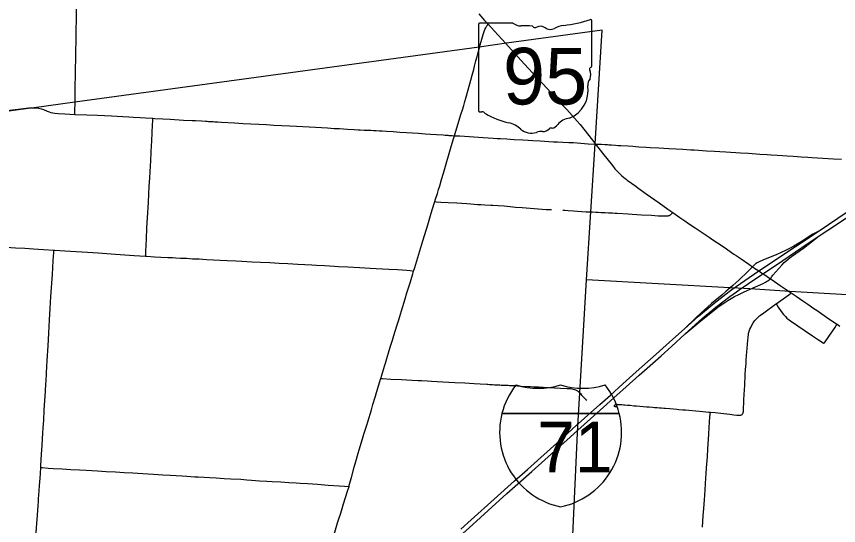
# Model space of a CAD drawing. Extents: x 9078 to 9739, y 4248 to 4966.
# Drawn here: x 9448.2 to 9549.3, y 4516.4 to 4579 of the extents above; entities that cross this region are included whole.
import ezdxf

# ---------------------------------------------------------------- set-up
doc = ezdxf.new("R2010")
doc.units = 0
for name, color, linetype in [('GM_X_County_Road', 7, 'Continuous'), ('GM_X_Interchange_Ramps', 7, 'Continuous'), ('GM_X_Interstate_Route', 7, 'Continuous'), ('GM_X_Interstate_Shield', 7, 'Continuous'), ('GM_X_State_Route', 7, 'Continuous'), ('GM_X_State_Shield', 7, 'Continuous'), ('GM_X_Township', 7, 'Continuous'), ('GM_X_Township_Road', 7, 'Continuous')]:
    doc.layers.add(name, color=color, linetype=linetype)

msp = doc.modelspace()

# ---------------------------------------------------------------- linework, layer by layer
at = {"layer": 'GM_X_County_Road'}
for points in [[(9505.17, 4575.29), (9505.23, 4575.54), (9505.43, 4576.26), (9505.6, 4576.81), (9505.73, 4577.2), (9505.82, 4577.42), (9505.92, 4577.65), (9506, 4577.79), (9506.07, 4577.9), (9506.12, 4577.97), (9506.2, 4578.08)], [(9502.08, 4564.37), (9502.16, 4564.65), (9502.49, 4565.75), (9502.9, 4567.08), (9503.04, 4567.56), (9503.21, 4568.1), (9503.35, 4568.58), (9503.46, 4568.97), (9503.76, 4570), (9504.09, 4571.18), (9504.26, 4571.81), (9504.45, 4572.53), (9504.55, 4572.93), (9504.71, 4573.56), (9504.86, 4574.12), (9505.07, 4574.91), (9505.17, 4575.29)], [(9499.66, 4556.26), (9499.75, 4556.55), (9499.97, 4557.26), (9500.11, 4557.73), (9500.25, 4558.2), (9500.49, 4558.99), (9500.72, 4559.77), (9500.88, 4560.32), (9501.14, 4561.19), (9501.35, 4561.9), (9501.6, 4562.76), (9501.93, 4563.86), (9502.08, 4564.37)], [(9519.43, 4563.34), (9520.16, 4563.31), (9520.57, 4563.29), (9520.9, 4563.27), (9521.06, 4563.25), (9521.4, 4563.23), (9521.86, 4563.2), (9522.2, 4563.18), (9522.23, 4563.18)], [(9522.23, 4563.18), (9522.53, 4563.16), (9523.43, 4563.1), (9524, 4563.06), (9524.74, 4563.01), (9525.64, 4562.96), (9526.13, 4562.93), (9527.19, 4562.87), (9528.42, 4562.8), (9529.32, 4562.74), (9530.14, 4562.7), (9531.12, 4562.64), (9531.53, 4562.62), (9532.1, 4562.58), (9533.08, 4562.52), (9534.06, 4562.46), (9534.71, 4562.43), (9535.45, 4562.37), (9536.02, 4562.34), (9536.67, 4562.3), (9537.25, 4562.27), (9538.23, 4562.2), (9539.62, 4562.1), (9540.52, 4562.04), (9541.01, 4562.02), (9541.74, 4561.97), (9542.4, 4561.92), (9542.97, 4561.88), (9543.71, 4561.84), (9544.69, 4561.77), (9545.51, 4561.72), (9546, 4561.69), (9546.73, 4561.65), (9548.7, 4561.52), (9549.68, 4561.46)], [(9497.05, 4547.7), (9497.18, 4548.16), (9498.19, 4551.45), (9498.62, 4552.87), (9498.78, 4553.42), (9499.04, 4554.28), (9499.21, 4554.83), (9499.57, 4556.01), (9499.66, 4556.26)], [(9437.86, 4551.19), (9438.03, 4551.18), (9438.28, 4551.17), (9438.93, 4551.13), (9439.91, 4551.07), (9440.89, 4551.02), (9441.96, 4550.95), (9444.25, 4550.82), (9445.64, 4550.73), (9446.95, 4550.65), (9448.1, 4550.59), (9449.24, 4550.53), (9450.31, 4550.46), (9451.53, 4550.38), (9452.8, 4550.3)], [(9451.19, 4523.54), (9451.21, 4523.8), (9451.3, 4525.19), (9451.36, 4526.25), (9451.45, 4527.81), (9451.49, 4528.38), (9451.55, 4529.36), (9451.61, 4530.59), (9451.66, 4531.24), (9451.73, 4532.31), (9451.77, 4532.96), (9451.82, 4533.86), (9451.84, 4534.19), (9451.9, 4535.17), (9451.95, 4535.99), (9451.99, 4536.72), (9452.09, 4538.53), (9452.17, 4540.08), (9452.27, 4541.72), (9452.35, 4543.11), (9452.44, 4544.58), (9452.62, 4547.28), (9452.67, 4548.1), (9452.72, 4549), (9452.78, 4549.98), (9452.8, 4550.3)], [(9452.8, 4550.3), (9452.93, 4550.3), (9454.15, 4550.21), (9456.93, 4550.03), (9458.24, 4549.94), (9460.37, 4549.79), (9462.66, 4549.64), (9464.09, 4549.54)], [(9464.09, 4549.54), (9464.22, 4549.54), (9465.2, 4549.48), (9465.94, 4549.44), (9466.83, 4549.39), (9467.41, 4549.37), (9467.82, 4549.35), (9468.39, 4549.32), (9469.13, 4549.29), (9469.86, 4549.24), (9470.68, 4549.2), (9471.58, 4549.15), (9474.12, 4549.02), (9475.19, 4548.97), (9475.92, 4548.94), (9477.15, 4548.87), (9478.21, 4548.82), (9479.36, 4548.75), (9480.51, 4548.69), (9481.57, 4548.63), (9482.8, 4548.56), (9484.52, 4548.47), (9485.09, 4548.43), (9486.07, 4548.38), (9487.3, 4548.32), (9487.79, 4548.29), (9488.94, 4548.22), (9490.41, 4548.14), (9491.72, 4548.07), (9492.46, 4548.03), (9494.01, 4547.94), (9495.08, 4547.89), (9496.22, 4547.83), (9496.63, 4547.79), (9496.88, 4547.76), (9497.05, 4547.7)], [(9493.01, 4534.51), (9493.12, 4534.9), (9493.46, 4536), (9493.58, 4536.39), (9493.84, 4537.25), (9493.96, 4537.65), (9494.18, 4538.35), (9494.44, 4539.22), (9494.6, 4539.77), (9494.77, 4540.32), (9495.01, 4541.1), (9495.21, 4541.73), (9495.42, 4542.43), (9495.55, 4542.82), (9496, 4544.31), (9496.22, 4545.02), (9496.61, 4546.27), (9496.95, 4547.37), (9497.05, 4547.7)], [(9541.62, 4543.67), (9542.5, 4544.3), (9543.17, 4544.78), (9543.36, 4544.93), (9543.48, 4545.02)], [(9538.3, 4540.28), (9538.32, 4540.33), (9538.4, 4540.56), (9538.5, 4540.78), (9538.65, 4541.07), (9538.81, 4541.35), (9538.9, 4541.49), (9539, 4541.62), (9539.16, 4541.8), (9539.34, 4541.97), (9539.58, 4542.19), (9539.71, 4542.29), (9540.11, 4542.58), (9541.57, 4543.63), (9541.62, 4543.67)], [(9541.62, 4543.67), (9541.7, 4543.56), (9541.87, 4543.29), (9542.25, 4542.75), (9542.54, 4542.36), (9542.65, 4542.23), (9542.76, 4542.11), (9542.93, 4541.94), (9543.12, 4541.79), (9543.39, 4541.6), (9546.1, 4539.76), (9546.84, 4539.25), (9547.41, 4538.87), (9547.46, 4538.86), (9547.5, 4538.85)], [(9547.5, 4538.85), (9547.55, 4538.87), (9547.59, 4538.9), (9548.11, 4539.65), (9548.48, 4540.19), (9548.85, 4540.74), (9549.03, 4541.02), (9549.13, 4541.18)], [(9537.64, 4531.51), (9537.66, 4531.85), (9537.71, 4532.59), (9537.73, 4533.08), (9537.77, 4533.73), (9537.79, 4534.14), (9537.81, 4534.47), (9537.84, 4535.04), (9537.88, 4535.61), (9537.93, 4536.35), (9537.96, 4536.84), (9537.99, 4537.25), (9538.03, 4537.82), (9538.06, 4538.14), (9538.1, 4538.8), (9538.13, 4539.12), (9538.17, 4539.61), (9538.21, 4539.85), (9538.25, 4540.09), (9538.3, 4540.28)], [(9489.1, 4521.23), (9489.14, 4521.37), (9489.4, 4522.32), (9489.75, 4523.58), (9489.94, 4524.3), (9490.23, 4525.32), (9490.34, 4525.72), (9490.63, 4526.66), (9490.85, 4527.36), (9490.94, 4527.65), (9491.1, 4528.14), (9491.29, 4528.77), (9491.41, 4529.16), (9491.85, 4530.66), (9492.04, 4531.29), (9492.35, 4532.31), (9492.49, 4532.78), (9492.78, 4533.72), (9492.99, 4534.43), (9493.01, 4534.51)], [(9493.01, 4534.51), (9493.2, 4534.5), (9494.26, 4534.43), (9495.57, 4534.36), (9496.88, 4534.3), (9497.62, 4534.26), (9498.03, 4534.24), (9498.76, 4534.2), (9499.25, 4534.17), (9500.64, 4534.09), (9502.12, 4534.01), (9503.34, 4533.95), (9504.49, 4533.89), (9505.23, 4533.84), (9506.04, 4533.79), (9506.19, 4533.79), (9506.36, 4533.78), (9506.53, 4533.77), (9506.76, 4533.76), (9506.98, 4533.74), (9507.22, 4533.73), (9507.43, 4533.72), (9507.63, 4533.71), (9507.81, 4533.7), (9508.01, 4533.69), (9508.16, 4533.68), (9508.35, 4533.67), (9508.49, 4533.67), (9508.68, 4533.66), (9508.82, 4533.65), (9509, 4533.64), (9509.55, 4533.62), (9509.8, 4533.6), (9510.05, 4533.58), (9510.29, 4533.57), (9511.19, 4533.52), (9511.43, 4533.51), (9511.84, 4533.49), (9512.41, 4533.46), (9512.99, 4533.44), (9513.64, 4533.4), (9515.11, 4533.33), (9515.93, 4533.29), (9516.34, 4533.26), (9516.5, 4533.24), (9516.66, 4533.2), (9516.82, 4533.15), (9516.97, 4533.09), (9517.12, 4533.01), (9517.19, 4532.97), (9517.26, 4532.93), (9517.32, 4532.89), (9517.38, 4532.83), (9517.44, 4532.78), (9517.51, 4532.7)], [(9517.51, 4532.7), (9517.55, 4532.66), (9517.71, 4532.47), (9517.92, 4532.22), (9518.09, 4532.05), (9518.22, 4531.92), (9518.33, 4531.82)], [(9535.2, 4530.2), (9535.56, 4530.16), (9535.94, 4530.11), (9536.41, 4530.05), (9536.81, 4530), (9536.88, 4530), (9537.12, 4529.97), (9537.21, 4529.98), (9537.29, 4530), (9537.37, 4530.03), (9537.44, 4530.08), (9537.5, 4530.14), (9537.54, 4530.21), (9537.57, 4530.3), (9537.6, 4530.46), (9537.61, 4530.62), (9537.62, 4530.97), (9537.64, 4531.39), (9537.64, 4531.51)], [(9532.58, 4516.22), (9532.67, 4517.61), (9532.74, 4518.51), (9532.81, 4519.58), (9532.84, 4520.15), (9532.89, 4520.8), (9532.95, 4521.54), (9532.99, 4522.27), (9533.03, 4522.76), (9533.08, 4523.5), (9533.14, 4524.4), (9533.17, 4524.89), (9533.23, 4525.79), (9533.26, 4526.44), (9533.35, 4527.67), (9533.39, 4528.49), (9533.47, 4529.8), (9533.5, 4530.08), (9533.55, 4530.36)], [(9533.55, 4530.36), (9534.14, 4530.32), (9534.84, 4530.24), (9535.2, 4530.2)], [(9450.37, 4511.94), (9450.41, 4512.43), (9450.49, 4513.58), (9450.58, 4514.89), (9450.63, 4515.54), (9450.71, 4516.68), (9450.79, 4517.67), (9450.88, 4518.89), (9450.91, 4519.38), (9450.93, 4519.71), (9450.97, 4520.2), (9451.01, 4520.69), (9451.05, 4521.34), (9451.11, 4522.24), (9451.15, 4522.81), (9451.19, 4523.54)], [(9484.91, 4507.84), (9484.96, 4507.99), (9485, 4508.13), (9485.15, 4508.61), (9485.39, 4509.39), (9485.74, 4510.48), (9486.07, 4511.5), (9486.78, 4513.77), (9487.23, 4515.18), (9487.44, 4515.88), (9487.7, 4516.75), (9487.85, 4517.22), (9488.08, 4517.92), (9488.44, 4519.09), (9488.68, 4519.88), (9488.92, 4520.66), (9489.1, 4521.23)]]:
    msp.add_lwpolyline(points, dxfattribs=at)
at = {"layer": 'GM_X_Interchange_Ramps'}
for points in [[(9546.79, 4552.6), (9546.15, 4552.25), (9544.71, 4551.31), (9544.22, 4551.01), (9543.79, 4550.76), (9543.29, 4550.49), (9542.78, 4550.23), (9542.26, 4549.99), (9541.73, 4549.76), (9539.98, 4549.05), (9539.53, 4548.85), (9539.31, 4548.74), (9539.17, 4548.66), (9539.11, 4548.61), (9538.93, 4548.44), (9538.73, 4548.25)], [(9540.92, 4546.76), (9541.09, 4547.03), (9541.13, 4547.1), (9541.24, 4547.23), (9542.34, 4548.45), (9542.62, 4548.75), (9542.86, 4548.98), (9543.11, 4549.19), (9543.51, 4549.49), (9544.98, 4550.54), (9546.94, 4552.03)], [(9538.73, 4548.25), (9538.16, 4547.66), (9537.03, 4546.59), (9536.3, 4545.94), (9535.69, 4545.4), (9535.49, 4545.23), (9534.94, 4544.77), (9533.69, 4543.72), (9532.77, 4542.92), (9531.78, 4542.01), (9530.35, 4540.62)], [(9530.46, 4539.99), (9532.17, 4541.41), (9533.03, 4542.14), (9533.79, 4542.76), (9534.24, 4543.12), (9534.64, 4543.41), (9535.19, 4543.77), (9535.67, 4544.08), (9536.09, 4544.34), (9536.52, 4544.58), (9537.03, 4544.84), (9537.62, 4545.13), (9537.62, 4545.13), (9538.44, 4545.5), (9540.02, 4546.19), (9540.32, 4546.34), (9540.46, 4546.42), (9540.59, 4546.51), (9540.8, 4546.66), (9540.92, 4546.76)]]:
    msp.add_lwpolyline(points, dxfattribs=at)
at = {"layer": 'GM_X_Interstate_Route'}
for points in [[(9541.67, 4548.5), (9544.79, 4550.61), (9546.94, 4552.03), (9547.99, 4552.73), (9550.78, 4554.61), (9552.34, 4555.66), (9553.08, 4556.18), (9553.87, 4556.76), (9554.59, 4557.3), (9555.43, 4557.96), (9556.39, 4558.73), (9556.62, 4558.91)], [(9502.86, 4515.98), (9504.14, 4517.13), (9506.95, 4519.65), (9509.45, 4521.9), (9511.04, 4523.32), (9512.69, 4524.8), (9514.65, 4526.55), (9515.99, 4527.75), (9517.09, 4528.74), (9517.28, 4528.91), (9518.07, 4529.62), (9519.96, 4531.32), (9521.24, 4532.47), (9522.77, 4533.83), (9524.42, 4535.31), (9526.86, 4537.5), (9528.09, 4538.59), (9529.31, 4539.68), (9530.35, 4540.62), (9532.08, 4542.17), (9534, 4543.77), (9535.87, 4545.22), (9536.16, 4545.43), (9537.76, 4546.55), (9539.51, 4547.73), (9544, 4550.75), (9546.79, 4552.6), (9550.5, 4555.1)], [(9539.9, 4547.3), (9540.01, 4547.38), (9541.67, 4548.5)], [(9538.27, 4546.21), (9539.81, 4547.25), (9539.9, 4547.3)], [(9502.67, 4515.08), (9504.32, 4516.56), (9506.21, 4518.25), (9508.53, 4520.34), (9510.25, 4521.86), (9511.59, 4523.07), (9513.18, 4524.49), (9514.4, 4525.59), (9516.29, 4527.29), (9517.23, 4528.13), (9518.79, 4529.53), (9520.38, 4530.96), (9521.66, 4532.11), (9523.19, 4533.47), (9524.78, 4534.89), (9525.77, 4535.78), (9527.47, 4537.3), (9528.75, 4538.45), (9530.46, 4539.99), (9532.55, 4541.88), (9534.22, 4543.27), (9535.93, 4544.59), (9536.75, 4545.17), (9537.07, 4545.4), (9538.25, 4546.2), (9538.27, 4546.21)]]:
    msp.add_lwpolyline(points, dxfattribs=at)
at = {"layer": 'GM_X_Interstate_Shield'}
for p, q in [((9507.91, 4530.2), (9522.34, 4530.2)), ((9522.34, 4530.2), (9507.91, 4530.2)), ((9522.34, 4530.2), (9507.91, 4530.2))]:
    msp.add_line(p, q, dxfattribs=at)
for centre, start, end in [((9517, 4527.9), 141.669, 165.8066), ((9512.38, 4542.68), 253.0091, 286.9909), ((9517.86, 4542.68), 253.0091, 286.9909), ((9513.25, 4527.9), 14.1934, 38.331), ((9517, 4527.9), 165.8066, 258.463), ((9513.25, 4527.9), 281.537, 14.1934)]:
    msp.add_arc(centre, 9.38, start, end, dxfattribs=at)
at = {"layer": 'GM_X_State_Route'}
for points in [[(9505.05, 4579.34), (9505.77, 4578.55), (9506.2, 4578.08), (9506.99, 4577.22), (9507.88, 4576.26), (9508.37, 4575.72), (9509.43, 4574.57), (9511.15, 4572.69), (9513.48, 4570.16), (9514.76, 4568.77), (9515.37, 4568.11), (9515.88, 4567.57), (9517.15, 4566.17), (9517.52, 4565.74), (9517.99, 4565.16), (9519.05, 4563.81), (9519.43, 4563.34), (9520.28, 4562.23), (9521.5, 4560.69), (9521.81, 4560.31), (9522.09, 4560.01), (9522.37, 4559.72), (9522.67, 4559.44), (9523.05, 4559.12), (9523.19, 4559)], [(9523.19, 4559), (9523.3, 4558.91), (9524.37, 4558.15), (9524.63, 4557.95), (9525.63, 4557.23), (9527.24, 4556.1), (9528.31, 4555.35), (9528.91, 4554.93), (9529.79, 4554.32), (9530.41, 4553.89)], [(9530.41, 4553.89), (9530.87, 4553.58), (9531.69, 4553.03), (9533.39, 4551.88), (9533.73, 4551.65), (9534.4, 4551.19), (9535.22, 4550.64), (9536.44, 4549.81), (9536.72, 4549.62)], [(9536.72, 4549.62), (9537.32, 4549.21), (9538.27, 4548.57), (9538.73, 4548.25), (9538.97, 4548.09)], [(9538.97, 4548.09), (9539.15, 4547.96), (9539.17, 4547.96)], [(9539.17, 4547.96), (9539.51, 4547.73), (9540.01, 4547.38), (9540.1, 4547.32), (9540.92, 4546.76), (9541.12, 4546.62), (9542.14, 4545.93), (9542.74, 4545.52)], [(9542.74, 4545.52), (9543.29, 4545.15), (9543.48, 4545.02), (9543.73, 4544.86)], [(9543.73, 4544.86), (9544.11, 4544.61), (9544.92, 4544.05), (9545.52, 4543.63), (9546.28, 4543.11)], [(9546.28, 4543.11), (9546.68, 4542.85), (9547.83, 4542.06), (9548.98, 4541.28), (9549.13, 4541.18), (9549.48, 4540.94)]]:
    msp.add_lwpolyline(points, dxfattribs=at)
at = {"layer": 'GM_X_State_Shield'}
for p, q in [((9505.03, 4578.03), (9505.03, 4567.47)), ((9509.25, 4578.22), (9505.17, 4578.22)), ((9518.95, 4572.95), (9518.95, 4578.48)), ((9518.95, 4572.95), (9518.95, 4572.95))]:
    msp.add_line(p, q, dxfattribs=at)
for centre, radius, start, end in [((9505.19, 4578.06), 0.161, 98.1301, 188.1301), ((9510.22, 4579.44), 1.56, 231.6195, 271.1119), ((9514, 4592.62), 14.76, 275.8445, 288.9065), ((9518.8, 4578.5), 0.155, 351.8621, 97.738), ((9510.74, 4572.28), 5.62, 80.4867, 94.9883), ((9512.01, 4578.11), 0.451, 219.7921, 297.1024), ((9512.67, 4576.89), 0.938, 54.4667, 119.1411), ((9513.89, 4578.57), 1.13, 233.8562, 294.8282), ((9515.88, 4574.99), 2.97, 97.3462, 120.7689), ((9518.79, 4572.93), 0.166, 289.6038, 7.7341), ((9518.92, 4572.54), 0.24, 107.944, 210.337), ((9517.39, 4571.85), 1.44, 340.033, 23.6496), ((9519.51, 4570.64), 1.05, 136.8065, 186.9296), ((9514.82, 4569.93), 3.69, 292.3089, 8.9858), ((9505.19, 4567.44), 0.163, 171.9584, 258.3066), ((9505.22, 4568.53), 1.24, 267.339, 280.6039), ((9505.47, 4566.86), 0.448, 29.7484, 93.2717), ((9511.13, 4576.35), 10.66, 240.4129, 257.1985), ((9507.95, 4562.72), 3.34, 47.1842, 75.836), ((9516.38, 4564.5), 2.02, 94.4031, 142.5768), ((9511.55, 4566.81), 2.12, 230.7004, 286.2918), ((9512.78, 4563.15), 1.74, 85.6951, 111.2099), ((9512.93, 4566.01), 1.13, 268.777, 315.5493), ((9513.95, 4564.99), 0.318, 65.7517, 132.6484), ((9513.82, 4566.44), 1.19, 282.8732, 323.2771)]:
    msp.add_arc(centre, radius, start, end, dxfattribs=at)
at = {"layer": 'GM_X_Township'}
for points in [[(9653.67, 4539.22), (9639.91, 4539.7), (9620, 4540.81), (9594.32, 4542.24), (9567.3, 4543.8), (9543.3, 4545.21), (9538.41, 4545.53), (9536.93, 4545.61), (9535.94, 4545.67), (9518.31, 4546.63), (9518.83, 4555), (9519.36, 4563.37), (9520.24, 4577.33), (9508.47, 4575.73), (9505.12, 4575.27), (9455.38, 4568.49), (9450.39, 4567.81), (9449.71, 4567.76), (9447.06, 4567.41)], [(9646.56, 4403.19), (9632.59, 4403.99), (9619.89, 4404.72), (9619.13, 4404.77), (9590.64, 4406.41), (9575.4, 4407.07), (9562.09, 4407.81), (9537.41, 4409.34), (9510.32, 4411.06), (9511.38, 4427.97), (9511.83, 4435.77), (9511.89, 4436.24), (9513.12, 4453.99), (9514.67, 4478.86), (9516.21, 4506.23), (9517.26, 4528.67), (9517.5, 4532.74), (9518.31, 4546.63)]]:
    msp.add_lwpolyline(points, dxfattribs=at)
at = {"layer": 'GM_X_Township_Road'}
for points in [[(9455.41, 4568.53), (9455.43, 4569.46), (9455.44, 4570.28), (9455.47, 4571.92), (9455.47, 4572.18), (9455.48, 4572.48), (9455.48, 4572.71), (9455.48, 4573.01), (9455.49, 4573.41), (9455.49, 4573.69), (9455.5, 4574.04), (9455.51, 4574.36), (9455.51, 4574.61), (9455.51, 4574.91), (9455.52, 4575.24), (9455.53, 4575.6), (9455.53, 4575.84), (9455.53, 4576.1), (9455.56, 4576.83), (9455.59, 4579.21), (9455.6, 4579.62), (9455.6, 4580.76), (9455.62, 4581.39)], [(9455.37, 4566.99), (9455.39, 4567.41), (9455.41, 4568.39), (9455.41, 4568.53)], [(9441.27, 4566.6), (9441.33, 4566.6), (9441.9, 4566.69), (9442.38, 4566.76), (9442.86, 4566.83), (9443.35, 4566.9), (9443.92, 4566.97), (9444.57, 4567.06), (9444.73, 4567.08), (9445.14, 4567.12), (9445.46, 4567.16), (9445.62, 4567.18), (9446.03, 4567.24), (9446.52, 4567.31), (9447.57, 4567.45), (9448.46, 4567.58), (9449.68, 4567.76), (9450.01, 4567.79), (9450.1, 4567.8)], [(9450.1, 4567.8), (9450.25, 4567.81), (9450.42, 4567.81), (9450.58, 4567.81), (9450.74, 4567.79), (9450.9, 4567.76), (9451.06, 4567.73), (9451.3, 4567.66), (9451.53, 4567.57), (9451.99, 4567.39), (9452.22, 4567.3), (9452.45, 4567.23), (9452.69, 4567.18), (9452.93, 4567.14), (9453.34, 4567.1), (9454.16, 4567.05), (9455.37, 4566.99)], [(9455.37, 4566.99), (9456.87, 4566.93), (9458.18, 4566.88), (9459.9, 4566.79), (9461.29, 4566.71), (9462.03, 4566.67), (9462.6, 4566.64), (9463.42, 4566.6), (9464.08, 4566.57), (9464.99, 4566.51)], [(9464.09, 4549.54), (9464.1, 4549.76), (9464.12, 4550.17), (9464.15, 4550.91), (9464.18, 4551.65), (9464.25, 4553.04), (9464.33, 4554.27), (9464.43, 4556.16), (9464.49, 4557.22), (9464.53, 4558.13), (9464.59, 4559.19), (9464.63, 4559.93), (9464.68, 4560.67), (9464.71, 4561.24), (9464.77, 4562.39), (9464.81, 4563.13), (9464.84, 4563.7), (9464.9, 4564.76), (9464.94, 4565.67), (9464.97, 4566.24), (9464.98, 4566.4), (9464.99, 4566.51)], [(9464.99, 4566.51), (9465.22, 4566.49), (9466.2, 4566.43), (9467.1, 4566.38), (9468.74, 4566.29), (9469.8, 4566.23), (9470.21, 4566.22), (9470.95, 4566.18), (9471.44, 4566.15), (9471.65, 4566.14), (9471.83, 4566.13), (9471.95, 4566.12), (9472.09, 4566.11), (9472.24, 4566.11), (9472.4, 4566.1), (9472.62, 4566.08), (9472.75, 4566.08), (9472.97, 4566.06), (9473.41, 4566.04), (9475.02, 4565.94), (9476.08, 4565.88), (9478.94, 4565.74), (9479.84, 4565.68), (9480.83, 4565.64), (9481.81, 4565.58), (9482.63, 4565.54), (9483.44, 4565.5), (9484.99, 4565.41), (9486.47, 4565.33), (9487.28, 4565.27), (9487.94, 4565.24), (9488.92, 4565.17), (9489.74, 4565.13), (9490.23, 4565.1), (9490.47, 4565.09), (9490.96, 4565.06), (9491.45, 4565.04), (9491.78, 4565.03), (9492.11, 4565.02), (9492.43, 4565), (9492.84, 4564.98), (9493.16, 4564.96), (9493.73, 4564.92), (9494.55, 4564.87), (9495.37, 4564.82), (9496.19, 4564.75), (9497.66, 4564.66), (9498.48, 4564.6), (9499.13, 4564.56), (9499.87, 4564.51), (9500.68, 4564.47), (9500.94, 4564.44), (9501.08, 4564.43), (9501.25, 4564.42), (9501.39, 4564.41), (9501.5, 4564.4), (9501.79, 4564.38), (9502.03, 4564.37), (9502.08, 4564.37)], [(9502.08, 4564.37), (9502.2, 4564.36), (9502.73, 4564.33), (9503.3, 4564.3), (9504.44, 4564.22), (9505.02, 4564.18), (9505.59, 4564.15), (9506.81, 4564.06), (9507.31, 4564.04), (9507.72, 4564.02), (9508.53, 4563.97), (9508.94, 4563.94), (9509.43, 4563.91), (9510.49, 4563.84), (9511.15, 4563.81), (9511.72, 4563.78), (9512.62, 4563.72), (9513.68, 4563.65), (9514.26, 4563.62), (9514.75, 4563.6), (9515.4, 4563.58), (9516.14, 4563.54), (9516.71, 4563.51), (9517.61, 4563.44), (9518.51, 4563.38), (9519.43, 4563.34)], [(9499.66, 4556.26), (9499.83, 4556.25), (9500.41, 4556.21), (9501.31, 4556.15), (9502.37, 4556.09), (9503.6, 4556.01), (9504.09, 4555.98), (9504.91, 4555.92), (9505.32, 4555.9), (9505.81, 4555.87), (9506.55, 4555.83), (9506.8, 4555.82), (9507.45, 4555.78), (9508.19, 4555.72), (9508.92, 4555.65), (9509.57, 4555.59), (9510.39, 4555.52), (9512.36, 4555.37), (9513.34, 4555.3), (9513.83, 4555.28), (9514, 4555.27)], [(9515.39, 4555.19), (9515.63, 4555.19), (9516.04, 4555.16), (9516.69, 4555.11), (9517.18, 4555.07), (9517.75, 4555.03), (9518.25, 4555.01), (9518.65, 4555), (9518.85, 4555)], [(9518.85, 4555), (9519.06, 4554.99), (9519.46, 4554.97), (9519.74, 4554.95), (9520.13, 4554.93), (9520.6, 4554.91), (9521, 4554.89), (9521.5, 4554.86), (9521.83, 4554.85), (9522.07, 4554.82), (9523.45, 4554.75), (9523.94, 4554.72), (9525.08, 4554.65), (9526.31, 4554.58), (9527.12, 4554.53), (9527.45, 4554.51), (9527.85, 4554.49), (9528.1, 4554.49), (9528.26, 4554.5), (9528.34, 4554.51), (9528.42, 4554.54), (9528.5, 4554.57), (9528.57, 4554.61), (9528.64, 4554.65), (9528.76, 4554.74), (9528.87, 4554.88), (9528.91, 4554.93)], [(9522.03, 4531.1), (9521.97, 4531.04), (9521.9, 4531.01), (9521.82, 4531.02), (9521.76, 4531.07), (9521.74, 4531.15), (9521.76, 4531.23), (9521.82, 4531.28), (9521.89, 4531.31), (9521.97, 4531.33), (9522.04, 4531.33), (9522.1, 4531.32), (9522.11, 4531.32), (9522.31, 4531.32), (9522.44, 4531.31), (9522.66, 4531.29), (9522.86, 4531.28), (9523.03, 4531.25), (9523.36, 4531.22), (9523.66, 4531.2), (9524.13, 4531.15), (9524.46, 4531.12), (9524.87, 4531.08), (9525.68, 4531.02), (9526.01, 4531), (9526.42, 4530.97), (9526.69, 4530.94), (9527, 4530.92), (9527.28, 4530.9), (9527.54, 4530.88), (9527.8, 4530.86), (9528.03, 4530.85), (9528.57, 4530.8), (9529.01, 4530.76), (9529.42, 4530.72), (9529.67, 4530.7), (9530.16, 4530.65), (9530.48, 4530.63), (9530.89, 4530.59), (9532.61, 4530.44), (9533.35, 4530.37), (9533.55, 4530.36)], [(9451.19, 4523.54), (9451.39, 4523.54), (9452.12, 4523.49), (9452.7, 4523.45), (9453.84, 4523.39), (9454.91, 4523.32), (9455.97, 4523.27), (9456.79, 4523.22), (9458.18, 4523.13), (9459.25, 4523.07), (9460.4, 4523), (9461.46, 4522.94), (9462.53, 4522.89), (9463.76, 4522.81), (9465.07, 4522.73), (9466.21, 4522.65), (9467.11, 4522.6), (9467.85, 4522.56), (9468.59, 4522.51), (9469.16, 4522.48), (9470.14, 4522.42), (9470.55, 4522.4), (9471.29, 4522.36), (9471.94, 4522.32), (9472.76, 4522.27), (9473.75, 4522.22), (9474.56, 4522.17), (9475.79, 4522.1), (9476.53, 4522.05), (9477.1, 4522.01), (9478.08, 4521.93), (9478.99, 4521.88), (9479.64, 4521.85), (9480.71, 4521.78), (9481.69, 4521.71), (9482.59, 4521.65), (9483.08, 4521.62), (9483.98, 4521.57), (9485.21, 4521.49), (9486.52, 4521.4), (9487.89, 4521.31), (9488.56, 4521.27), (9489.1, 4521.23)]]:
    msp.add_lwpolyline(points, dxfattribs=at)

# ---------------------------------------------------------------- texts
at = {"layer": 'GM_X_Interstate_Shield'}
msp.add_text('71', height=6.25, dxfattribs=at).set_placement((9512.23, 4522.94))
at = {"layer": 'GM_X_State_Shield'}
msp.add_text('95', height=6.961, dxfattribs=at).set_placement((9508.04, 4568.21))

doc.saveas('drawing.dxf')
